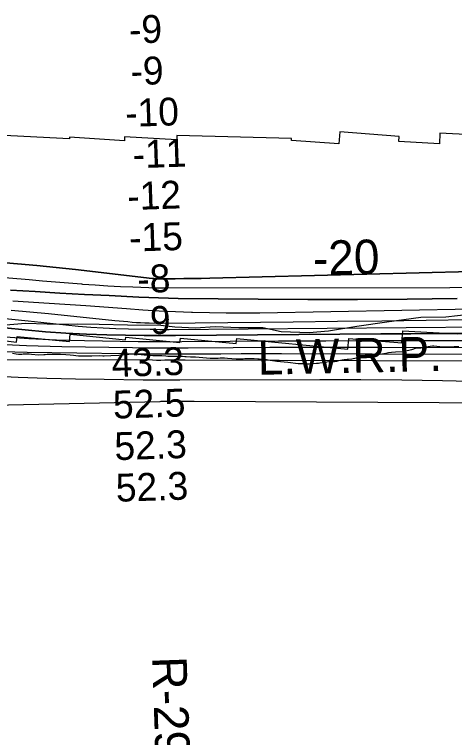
# Model space of a CAD drawing. Extents: x 3192986 to 3230865, y 867483 to 892886.
# Drawn here: x 3199431 to 3200491, y 876124 to 877863 of the extents above; entities that cross this region are included whole.
import ezdxf

# ---------------------------------------------------------------- set-up
doc = ezdxf.new("R2010")
doc.units = 0
for name, color, linetype in [('V-RIVR-EDGE', 7, 'Continuous'), ('V-RIVR-RANG', 7, 'Continuous'), ('V-RIVR-RANG-IDEN', 7, 'Continuous'), ('V-RRAP-RVMT', 7, 'Continuous'), ('V-SITE-VEGE', 7, 'Continuous'), ('V-TOPO-DPTH', 7, 'Continuous'), ('V-TOPO-MAJR', 7, 'Continuous'), ('V-TOPO-MINR', 7, 'Continuous'), ('V-TOPO-MINR-IDEN', 7, 'Continuous'), ('V-TOPO-WATR', 7, 'Continuous'), ('V-TOPO-WATR-IDEN', 7, 'Continuous')]:
    doc.layers.add(name, color=color, linetype=linetype)

msp = doc.modelspace()

# ---------------------------------------------------------------- linework, layer by layer
at = {"layer": 'V-RIVR-EDGE'}
msp.add_lwpolyline([(3199401.5, 877115.9), (3199457.8, 877120.5), (3199509.8, 877118.5), (3199560.8, 877117.9), (3199582.3, 877118.8), (3199635.7, 877117.7), (3199703.4, 877116.6), (3199783.5, 877115.4), (3199817.8, 877111.5), (3199867.4, 877109), (3199914.2, 877112.2), (3199971.9, 877109.7), (3200029.6, 877109.6), (3200073.4, 877100.4), (3200141.1, 877098.3), (3200187.4, 877102), (3200255.6, 877112.8), (3200327.6, 877123.6), (3200409.7, 877134.4), (3200469.8, 877135.2), (3200526.1, 877141.7)], dxfattribs=at)
at = {"layer": 'V-RRAP-RVMT'}
for p, q in [((3199563.5, 877563.5), (3199303.6, 877577.3)), ((3199563.9, 877567.9), (3199563.5, 877563.5)), ((3199696.2, 877558.7), (3199563.9, 877567.9)), ((3199696.5, 877568.7), (3199696.2, 877558.7)), ((3199822.4, 877561.5), (3199696.5, 877568.7)), ((3199822.6, 877571.8), (3199822.4, 877561.5)), ((3200098, 877564.1), (3199822.6, 877571.8)), ((3200214.9, 877580.3), (3200212.5, 877551.3)), ((3200357.6, 877569.1), (3200214.9, 877580.3)), ((3200356.6, 877556.9), (3200357.6, 877569.1)), ((3200455.7, 877577.1), (3200454.4, 877551.7)), ((3200584.8, 877570.1), (3200455.7, 877577.1)), ((3200098.1, 877559.2), (3200098, 877564.1)), ((3200212.5, 877551.3), (3200098.1, 877559.2)), ((3200454.4, 877551.7), (3200356.6, 877556.9)), ((3200364.1, 877073.4), (3200366.2, 877102.1)), ((3200366.2, 877102.1), (3200497.5, 877094.5)), ((3199303.8, 877090.1), (3199436.5, 877074.8)), ((3199436.5, 877074.8), (3199437.9, 877088.3)), ((3199437.9, 877088.3), (3199564.1, 877076.1)), ((3199564.1, 877076.1), (3199565.8, 877093.5)), ((3199565.8, 877093.5), (3199698.5, 877080.1)), ((3199698.5, 877080.1), (3199699.2, 877086.7)), ((3199699.2, 877086.7), (3199829.9, 877074.2)), ((3199829.9, 877074.2), (3199831, 877084.6)), ((3199831, 877084.6), (3199965.2, 877071.2)), ((3199965.2, 877071.2), (3199966.5, 877083.5)), ((3199966.5, 877083.5), (3200233.6, 877057.8)), ((3200233.6, 877057.8), (3200236.2, 877083.3)), ((3200236.2, 877083.3), (3200364.1, 877073.4))]:
    msp.add_line(p, q, dxfattribs=at)
at = {"layer": 'V-SITE-VEGE'}
for p, q in [((3200427.5, 877063.7), (3200409.7, 877060.4)), ((3200432.5, 877064.5), (3200427.5, 877063.7)), ((3200437.8, 877065.1), (3200432.5, 877064.5)), ((3200441.4, 877065.1), (3200437.8, 877065.1)), ((3200448.5, 877064.6), (3200441.4, 877065.1)), ((3200455.2, 877063.6), (3200448.5, 877064.6)), ((3200462.6, 877062.8), (3200455.2, 877063.6)), ((3200467.7, 877062.6), (3200462.6, 877062.8)), ((3200481.1, 877062.5), (3200467.7, 877062.6)), ((3200485.5, 877062.7), (3200481.1, 877062.5)), ((3200489.7, 877063.1), (3200485.5, 877062.7)), ((3200500.9, 877063.4), (3200489.7, 877063.1)), ((3199435.9, 877046.2), (3199426.8, 877047.2)), ((3199441.2, 877045.2), (3199435.9, 877046.2)), ((3199444.4, 877044.8), (3199441.2, 877045.2)), ((3199449, 877045), (3199444.4, 877044.8)), ((3199452.5, 877045.5), (3199449, 877045)), ((3199456.9, 877045.9), (3199452.5, 877045.5)), ((3199461.2, 877045.7), (3199456.9, 877045.9)), ((3199466.8, 877045.7), (3199461.2, 877045.7)), ((3199472.5, 877045.3), (3199466.8, 877045.7)), ((3199488.9, 877043.6), (3199472.5, 877045.3)), ((3199501.8, 877044.2), (3199488.9, 877043.6)), ((3199505, 877044.1), (3199501.8, 877044.2)), ((3199509.9, 877044.7), (3199505, 877044.1)), ((3199514.3, 877044.9), (3199509.9, 877044.7)), ((3199519.4, 877044.9), (3199514.3, 877044.9)), ((3199528.9, 877045.4), (3199519.4, 877044.9)), ((3199534.7, 877045.4), (3199528.9, 877045.4)), ((3199542.6, 877045), (3199534.7, 877045.4)), ((3199555.2, 877044), (3199542.6, 877045)), ((3199714.6, 877045.7), (3199682.9, 877042.7)), ((3199719.3, 877045.7), (3199714.6, 877045.7)), ((3199736.4, 877044.6), (3199719.3, 877045.7)), ((3199743.7, 877043.6), (3199736.4, 877044.6)), ((3200315.9, 877045.8), (3200299.5, 877043.4)), ((3200325.2, 877047.5), (3200315.9, 877045.8)), ((3200332, 877049.1), (3200325.2, 877047.5)), ((3200339.1, 877050.2), (3200332, 877049.1)), ((3200348.4, 877051), (3200339.1, 877050.2)), ((3200366.6, 877051.5), (3200348.4, 877051)), ((3200370.1, 877051.9), (3200366.6, 877051.5)), ((3200387.4, 877056.4), (3200370.1, 877051.9)), ((3200398.3, 877059.9), (3200387.4, 877056.4)), ((3200406.6, 877060), (3200398.3, 877059.9)), ((3200409.7, 877060.4), (3200406.6, 877060)), ((3199565.3, 877043.3), (3199555.2, 877044)), ((3199573.2, 877042.5), (3199565.3, 877043.3)), ((3199579.2, 877042.1), (3199573.2, 877042.5)), ((3199585.5, 877041.3), (3199579.2, 877042.1)), ((3199592.6, 877040.8), (3199585.5, 877041.3)), ((3199600.8, 877040.8), (3199592.6, 877040.8)), ((3199603.9, 877041), (3199600.8, 877040.8)), ((3199617.4, 877041.1), (3199603.9, 877041)), ((3199635.2, 877041.7), (3199617.4, 877041.1)), ((3199643.9, 877041.2), (3199635.2, 877041.7)), ((3199647.5, 877041.2), (3199643.9, 877041.2)), ((3199663.5, 877041.6), (3199647.5, 877041.2)), ((3199682.9, 877042.7), (3199663.5, 877041.6)), ((3199754, 877042.6), (3199743.7, 877043.6)), ((3199764.6, 877041.8), (3199754, 877042.6)), ((3199780.1, 877041.9), (3199764.6, 877041.8)), ((3199786.4, 877041.7), (3199780.1, 877041.9)), ((3199795.5, 877040.7), (3199786.4, 877041.7)), ((3199800.5, 877040.2), (3199795.5, 877040.7)), ((3199805.8, 877040), (3199800.5, 877040.2)), ((3199812.5, 877040.2), (3199805.8, 877040)), ((3199819.7, 877040.2), (3199812.5, 877040.2)), ((3199836.3, 877039.9), (3199819.7, 877040.2)), ((3199841.2, 877039.5), (3199836.3, 877039.9)), ((3199844.6, 877039.5), (3199841.2, 877039.5)), ((3199855.1, 877038.8), (3199844.6, 877039.5)), ((3199859.2, 877038.4), (3199855.1, 877038.8)), ((3199867, 877038.2), (3199859.2, 877038.4)), ((3199902.8, 877035.3), (3199867, 877038.2)), ((3199907.1, 877035.1), (3199902.8, 877035.3)), ((3199922.2, 877035.2), (3199907.1, 877035.1)), ((3199926.9, 877035.8), (3199922.2, 877035.2)), ((3199931.5, 877036), (3199926.9, 877035.8)), ((3199936.8, 877036), (3199931.5, 877036)), ((3199944.5, 877035.5), (3199936.8, 877036)), ((3199965.3, 877033.7), (3199944.5, 877035.5)), ((3199969.7, 877033.5), (3199965.3, 877033.7)), ((3199974.2, 877033.4), (3199969.7, 877033.5)), ((3199981.6, 877033.8), (3199974.2, 877033.4)), ((3199986.1, 877034.4), (3199981.6, 877033.8)), ((3199994.8, 877034.6), (3199986.1, 877034.4)), ((3199999.6, 877034.9), (3199994.8, 877034.6)), ((3200008.5, 877034.7), (3199999.6, 877034.9)), ((3200017.2, 877033.9), (3200008.5, 877034.7)), ((3200020.9, 877033.9), (3200017.2, 877033.9)), ((3200024.7, 877033.3), (3200020.9, 877033.9)), ((3200028.5, 877033.2), (3200024.7, 877033.3)), ((3200034, 877032.8), (3200028.5, 877033.2)), ((3200038.4, 877031.8), (3200034, 877032.8)), ((3200046.9, 877030.4), (3200038.4, 877031.8)), ((3200057.9, 877029.2), (3200046.9, 877030.4)), ((3200063.3, 877028.4), (3200057.9, 877029.2)), ((3200068, 877028.1), (3200063.3, 877028.4)), ((3200072.2, 877027.7), (3200068, 877028.1)), ((3200089.6, 877025.5), (3200072.2, 877027.7)), ((3200188.2, 877027.2), (3200178.6, 877026)), ((3200202.2, 877027.7), (3200188.2, 877027.2)), ((3200207, 877028.3), (3200202.2, 877027.7)), ((3200211.7, 877029.5), (3200207, 877028.3)), ((3200225.4, 877031.8), (3200211.7, 877029.5)), ((3200232.5, 877032.6), (3200225.4, 877031.8)), ((3200235.7, 877033.2), (3200232.5, 877032.6)), ((3200244, 877034.1), (3200235.7, 877033.2)), ((3200261.4, 877037.4), (3200244, 877034.1)), ((3200269, 877039.6), (3200261.4, 877037.4)), ((3200275.7, 877040.7), (3200269, 877039.6)), ((3200286.6, 877041.7), (3200275.7, 877040.7)), ((3200290.4, 877042.3), (3200286.6, 877041.7)), ((3200295.5, 877043.3), (3200290.4, 877042.3)), ((3200299.5, 877043.4), (3200295.5, 877043.3)), ((3200114.5, 877022.8), (3200089.6, 877025.5)), ((3200127.8, 877022.8), (3200114.5, 877022.8)), ((3200128.4, 877022.9), (3200127.8, 877022.8)), ((3200133.3, 877022.1), (3200128.4, 877022.9)), ((3200139.8, 877022), (3200133.3, 877022.1)), ((3200146.6, 877022.4), (3200139.8, 877022)), ((3200158.2, 877023.7), (3200146.6, 877022.4)), ((3200163, 877023.7), (3200158.2, 877023.7)), ((3200166.2, 877023.9), (3200163, 877023.7)), ((3200178.6, 877026), (3200166.2, 877023.9))]:
    msp.add_line(p, q, dxfattribs=at)
at = {"layer": 'V-TOPO-DPTH'}
for points in [[(3199391.4, 877266.6), (3199485, 877258.7), (3199578.5, 877249.1), (3199762.7, 877227.8), (3199766.8, 877227.4), (3199770.8, 877227), (3199775.7, 877226.8), (3199777.4, 877226.8), (3199778, 877226.8), (3199818.4, 877227.1), (3199839.2, 877227.4), (3199860, 877227.7), (3199880.7, 877228.1), (3199901.5, 877228.6), (3200657.5, 877247.8)], [(3200657.5, 877247.8), (3199901.5, 877228.6), (3199880.7, 877228.1), (3199860, 877227.7), (3199839.2, 877227.4), (3199818.4, 877227.1), (3199778, 877226.8), (3199777.4, 877226.8), (3199775.7, 877226.8), (3199770.8, 877227), (3199766.8, 877227.4), (3199762.7, 877227.8), (3199578.5, 877249.1), (3199485, 877258.7), (3199391.4, 877266.6)], [(3200497, 877180), (3200377.2, 877178.4), (3200257.5, 877177.4), (3200137.7, 877177.5), (3200018, 877178.1), (3199825.8, 877180), (3199802.1, 877180.4), (3199778.4, 877181), (3199754.8, 877181.9), (3199731.1, 877182.9), (3199659.7, 877186.5), (3199600.3, 877189.6), (3199540.9, 877192.8), (3199481.6, 877196.1), (3199422.2, 877199.6)], [(3200497, 877180), (3200377.2, 877178.4), (3200257.5, 877177.4), (3200137.7, 877177.5), (3200018, 877178.1), (3199825.8, 877180), (3199802.1, 877180.4), (3199778.4, 877181), (3199754.8, 877181.9), (3199731.1, 877182.9), (3199659.7, 877186.5), (3199600.3, 877189.6), (3199540.9, 877192.8), (3199481.6, 877196.1), (3199422.2, 877199.6)], [(3199423.3, 877151.6), (3199513.5, 877143.2), (3199673.3, 877127.1), (3199683.6, 877126.1), (3199693.9, 877125.1), (3199704.2, 877124.1), (3199714.5, 877123.1), (3199724.8, 877122.2), (3199735.1, 877121.6), (3199745.5, 877121.1), (3199755.8, 877120.8), (3199772.9, 877120.5), (3199776.7, 877120.5), (3199780.5, 877120.4), (3199784.3, 877120.4), (3199788.1, 877120.4), (3200102.6, 877123.6), (3200209.3, 877124.8), (3200316, 877126), (3200422.6, 877127.4), (3200529.3, 877128.9)], [(3199423.3, 877151.6), (3199513.5, 877143.2), (3199673.3, 877127.1), (3199683.6, 877126.1), (3199693.9, 877125.1), (3199704.2, 877124.1), (3199714.5, 877123.1), (3199724.8, 877122.2), (3199735.1, 877121.6), (3199745.5, 877121.1), (3199755.8, 877120.8), (3199772.9, 877120.5), (3199776.7, 877120.5), (3199780.5, 877120.4), (3199784.3, 877120.4), (3199788.1, 877120.4), (3200102.6, 877123.6), (3200209.3, 877124.8), (3200316, 877126), (3200422.6, 877127.4), (3200529.3, 877128.9)], [(3200529.7, 877095.3), (3200457.5, 877095.1), (3200385.4, 877094.8), (3200313.2, 877094.3), (3199819.1, 877090.7), (3199800.3, 877090.6), (3199781.5, 877090.6), (3199762.8, 877090.8), (3199744, 877091), (3199653.9, 877092.5), (3199604.6, 877094), (3199555.4, 877096.2), (3199506.3, 877099.7), (3199457.2, 877104), (3199408.2, 877108.9)]]:
    msp.add_lwpolyline(points, dxfattribs=at)
at = {"layer": 'V-TOPO-MAJR'}
msp.add_lwpolyline([(3199370.9, 877052.7), (3199461.9, 877050.4), (3199701.3, 877047.3), (3199742.2, 877046.8), (3199783, 877046.6), (3199823.9, 877046.5), (3199864.8, 877046.7), (3199880, 877046.8), (3199928.5, 877047), (3199977, 877047.1), (3200025.4, 877047.1), (3200073.9, 877047.1), (3200729.8, 877045.3)], dxfattribs=at)
at = {"layer": 'V-TOPO-MINR'}
for points in [[(3199391.4, 877266.6), (3199485, 877258.7), (3199578.5, 877249.1), (3199762.7, 877227.8), (3199766.8, 877227.4), (3199770.8, 877227), (3199775.7, 877226.8), (3199777.4, 877226.8), (3199778, 877226.8), (3199818.4, 877227.1), (3199839.2, 877227.4), (3199860, 877227.7), (3199880.7, 877228.1), (3199901.5, 877228.6), (3200657.5, 877247.8)], [(3199378, 877232.7), (3199467.1, 877225), (3199498.5, 877222.3), (3199530, 877219.7), (3199561.5, 877217.1), (3199592.9, 877214.6), (3199595.1, 877214.5), (3199625.5, 877212.3), (3199655.9, 877210.3), (3199686.3, 877208.7), (3199716.7, 877207.4), (3199754.7, 877205.9), (3199766.2, 877205.5), (3199777.6, 877205.2), (3199789, 877205.1), (3199800.5, 877205), (3200479.2, 877206.4), (3200522, 877206.6)], [(3199422.2, 877199.6), (3199481.6, 877196.1), (3199540.9, 877192.8), (3199600.3, 877189.6), (3199659.7, 877186.5), (3199731.1, 877182.9), (3199754.8, 877181.9), (3199778.4, 877181), (3199802.1, 877180.4), (3199825.8, 877180), (3200018, 877178.1), (3200137.7, 877177.5), (3200257.5, 877177.4), (3200377.2, 877178.4), (3200497, 877180)], [(3199427.1, 877174.1), (3199515.2, 877168.6), (3199603.3, 877162.5), (3199701.3, 877155.3), (3199740.4, 877152.6), (3199779.5, 877150.3), (3199818.7, 877148.4), (3199857.8, 877146.9), (3199860.4, 877146.8), (3199900.8, 877145.8), (3199941.3, 877145.1), (3199981.8, 877145.1), (3200022.2, 877145.5), (3200705.8, 877157.7)], [(3199385.3, 877133.8), (3199464.6, 877125.6), (3199494.7, 877122.5), (3199524.8, 877119.4), (3199554.9, 877116.4), (3199585, 877113.5), (3199615.1, 877110.9), (3199645.3, 877108.9), (3199675.5, 877107.5), (3199705.7, 877106.6), (3199758.4, 877105.7), (3199769.7, 877105.6), (3199781, 877105.5), (3199792.3, 877105.5), (3199803.6, 877105.5), (3200564.6, 877111.6)], [(3199408.2, 877108.9), (3199457.2, 877104), (3199506.3, 877099.7), (3199555.4, 877096.2), (3199604.6, 877094), (3199653.9, 877092.5), (3199744, 877091), (3199762.8, 877090.8), (3199781.5, 877090.6), (3199800.3, 877090.6), (3199819.1, 877090.7), (3200313.2, 877094.3), (3200385.4, 877094.8), (3200457.5, 877095.1), (3200529.7, 877095.3)], [(3199398.3, 877088.5), (3199465.6, 877083.6), (3199532.9, 877080.5), (3199600.4, 877078.5), (3199729.6, 877076.4), (3199755.8, 877076.1), (3199782, 877075.9), (3199808.2, 877075.8), (3199834.4, 877075.9), (3200067.3, 877077.5), (3200180.7, 877078.1), (3200294, 877078.6), (3200407.4, 877078.8), (3200520.8, 877078.7)], [(3199375.7, 877071), (3199460.5, 877067), (3199545.3, 877064.5), (3199715.4, 877061.9), (3199749, 877061.4), (3199782.5, 877061.2), (3199816.1, 877061.1), (3199849.7, 877061.2), (3199958.2, 877061.9), (3200046.1, 877062.4), (3200133.9, 877062.7), (3200221.8, 877062.7), (3200309.6, 877062.7), (3200711.7, 877061.9)], [(3199269.1, 877033.3), (3199763.9, 877031.8), (3199773.7, 877031.7), (3199783.5, 877031.7), (3199793.4, 877031.8), (3199803.2, 877031.8), (3199813.1, 877031.8), (3199822.9, 877031.9), (3199832.8, 877031.9), (3199842.6, 877031.8), (3200747.9, 877028.8)], [(3199371.1, 876993.7), (3199440, 876990.6), (3199509, 876988.1), (3199578.1, 876986.5), (3199647.1, 876985.4), (3199741.2, 876984.5), (3199763.2, 876984.3), (3199785.2, 876984.2), (3199807.2, 876984.1), (3199829.2, 876984.2), (3200166.8, 876985.1), (3200265.3, 876984.9), (3200363.7, 876984.1), (3200462.1, 876982.3), (3200560.4, 876980)], [(3199087.5, 876916.5), (3199782.5, 876932.4), (3199784.7, 876932.5), (3199789.2, 876932.6), (3199791.4, 876932.6), (3199812.7, 876932.9), (3199825.6, 876933), (3199838.5, 876933.1), (3199851.3, 876933.1), (3199864.2, 876933), (3200748.2, 876928.3)]]:
    msp.add_lwpolyline(points, dxfattribs=at)
at = {"layer": 'V-TOPO-WATR'}
msp.add_lwpolyline([(3199423.3, 877151.6), (3199513.5, 877143.2), (3199673.3, 877127.1), (3199683.6, 877126.1), (3199693.9, 877125.1), (3199704.2, 877124.1), (3199714.5, 877123.1), (3199724.8, 877122.2), (3199735.1, 877121.6), (3199745.5, 877121.1), (3199755.8, 877120.8), (3199772.9, 877120.5), (3199776.7, 877120.5), (3199780.5, 877120.4), (3199784.3, 877120.4), (3199788.1, 877120.4), (3200102.6, 877123.6), (3200209.3, 877124.8), (3200316, 877126), (3200422.6, 877127.4), (3200529.3, 877128.9)], dxfattribs=at)

# ---------------------------------------------------------------- texts
at = {"layer": 'V-RIVR-RANG'}
for s, rotation, p in [('-9', 1.9673, (3199708.3, 877792.4)), ('-9', 1.9673, (3199711.8, 877692.4)), ('-10', 1.9673, (3199698.9, 877591.9)), ('-11', 1.9673, (3199717, 877492.5)), ('-12', 1.9673, (3199703.9, 877392)), ('-15', 1.9673, (3199708.4, 877292.1)), ('-8', 1.9673, (3199728.1, 877192.7)), ('9', 1.9673, (3199758.7, 877093.7)), ('43.3', 1.8283, (3199666.1, 876990.7)), ('52.5', 1.8283, (3199669.5, 876890.8)), ('52.3', 1.8283, (3199673, 876790.8)), ('52.3', 1.8283, (3199676.4, 876690.9))]:
    msp.add_text(s, height=67, rotation=rotation, dxfattribs=at).set_placement(p)
at = {"layer": 'V-RIVR-RANG-IDEN'}
msp.add_text('R-294.3', height=83, rotation=271.9666, dxfattribs=at).set_placement((3199762.8, 876317.8))
at = {"layer": 'V-TOPO-MINR-IDEN'}
msp.add_text('-20', height=83, rotation=1.4582, dxfattribs=at).set_placement((3200150.8, 877234.9))
at = {"layer": 'V-TOPO-WATR-IDEN'}
msp.add_text('L.W.R.P.', height=83, rotation=1.2311, dxfattribs=at).set_placement((3200017.7, 876996.1))

doc.saveas('drawing.dxf')
